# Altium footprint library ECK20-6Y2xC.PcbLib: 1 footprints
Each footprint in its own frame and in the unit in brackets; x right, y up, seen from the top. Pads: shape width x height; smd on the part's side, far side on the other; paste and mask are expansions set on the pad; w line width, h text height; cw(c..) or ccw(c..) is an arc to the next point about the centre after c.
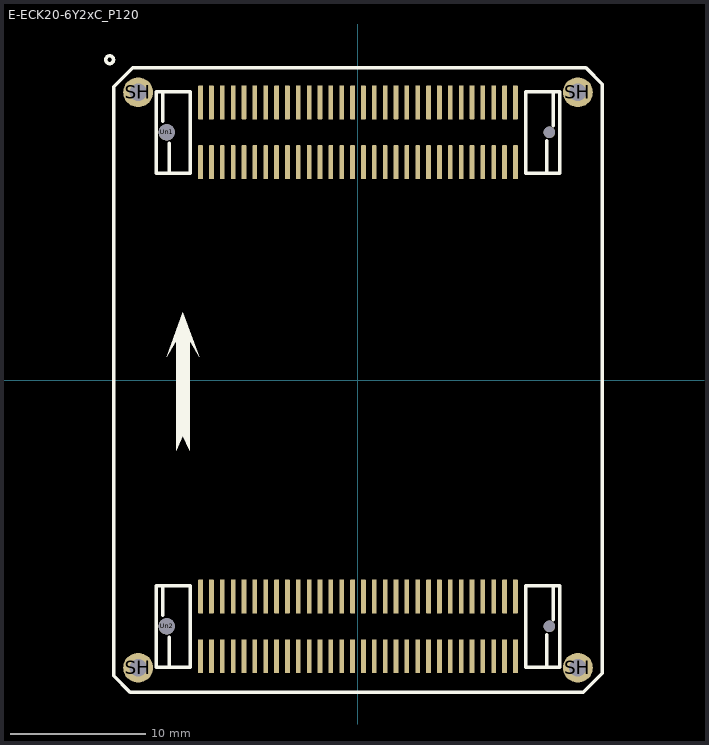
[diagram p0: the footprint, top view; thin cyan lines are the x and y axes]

## E-ECK20-6Y2xC_P120 [mm]
pads (128):
  rrect25% 0.35x2.5 smd: J1_1(-11.6,20.45) J1_2(-10.8,20.45) J1_3(-10,20.45) J1_4(-9.2,20.45) J1_5(-8.4,20.45) J1_6(-7.6,20.45) J1_7(-6.8,20.45) J1_8(-6,20.45) J1_9(-5.2,20.45) J1_10(-4.4,20.45) J1_11(-3.6,20.45) J1_12(-2.8,20.45) J1_13(-2,20.45) J1_14(-1.2,20.45) J1_15(-0.4,20.45) J1_16(0.4,20.45) J1_17(1.2,20.45) J1_18(2,20.45) J1_19(2.8,20.45) J1_20(3.6,20.45) J1_21(4.4,20.45) J1_22(5.2,20.45) J1_23(6,20.45) J1_24(6.8,20.45) J1_25(7.6,20.45) J1_26(8.4,20.45) J1_27(9.2,20.45) J1_28(10,20.45) J1_29(10.8,20.45) J1_30(11.6,20.45) J1_31(11.6,16.05) J1_32(10.8,16.05) J1_33(10,16.05) J1_34(9.2,16.05) J1_35(8.4,16.05) J1_36(7.6,16.05) J1_37(6.8,16.05) J1_38(6,16.05) J1_39(5.2,16.05) J1_40(4.4,16.05) J1_41(3.6,16.05) J1_42(2.8,16.05) J1_43(2,16.05) J1_44(1.2,16.05) J1_45(0.4,16.05) J1_46(-0.4,16.05) J1_47(-1.2,16.05) J1_48(-2,16.05) J1_49(-2.8,16.05) J1_50(-3.6,16.05) J1_51(-4.4,16.05) J1_52(-5.2,16.05) J1_53(-6,16.05) J1_54(-6.8,16.05) J1_55(-7.6,16.05) J1_56(-8.4,16.05) J1_57(-9.2,16.05) J1_58(-10,16.05) J1_59(-10.8,16.05) J1_60(-11.6,16.05) J2_1(-11.6,-15.95) J2_2(-10.8,-15.95) J2_3(-10,-15.95) J2_4(-9.2,-15.95) J2_5(-8.4,-15.95) J2_6(-7.6,-15.95) J2_7(-6.8,-15.95) J2_8(-6,-15.95) J2_9(-5.2,-15.95) J2_10(-4.4,-15.95) J2_11(-3.6,-15.95) J2_12(-2.8,-15.95) J2_13(-2,-15.95) J2_14(-1.2,-15.95) J2_15(-0.4,-15.95) J2_16(0.4,-15.95) J2_17(1.2,-15.95) J2_18(2,-15.95) J2_19(2.8,-15.95) J2_20(3.6,-15.95) J2_21(4.4,-15.95) J2_22(5.2,-15.95) J2_23(6,-15.95) J2_24(6.8,-15.95) J2_25(7.6,-15.95) J2_26(8.4,-15.95) J2_27(9.2,-15.95) J2_28(10,-15.95) J2_29(10.8,-15.95) J2_30(11.6,-15.95) J2_31(11.6,-20.35) J2_32(10.8,-20.35) J2_33(10,-20.35) J2_34(9.2,-20.35) J2_35(8.4,-20.35) J2_36(7.6,-20.35) J2_37(6.8,-20.35) J2_38(6,-20.35) J2_39(5.2,-20.35) J2_40(4.4,-20.35) J2_41(3.6,-20.35) J2_42(2.8,-20.35) J2_43(2,-20.35) J2_44(1.2,-20.35) J2_45(0.4,-20.35) J2_46(-0.4,-20.35) J2_47(-1.2,-20.35) J2_48(-2,-20.35) J2_49(-2.8,-20.35) J2_50(-3.6,-20.35) J2_51(-4.4,-20.35) J2_52(-5.2,-20.35) J2_53(-6,-20.35) J2_54(-6.8,-20.35) J2_55(-7.6,-20.35) J2_56(-8.4,-20.35) J2_57(-9.2,-20.35) J2_58(-10,-20.35) J2_59(-10.8,-20.35) J2_60(-11.6,-20.35)
  round 2.2 hole 1.3: SH(-16.2,-21.2) SH(-16.2,21.2) SH(16.2,-21.2) SH(16.2,21.2)
  round 1.2 hole 1.2: Un1(-14.1,18.25) Un2(-14.1,-18.15)
  round 0.84 hole 0.84: Un3(14.1,18.25) Un4(14.1,-18.15)
F.SilkS:
  circle w0.254: c-18.3,23.6 r0.288
  region: -11.7,1.7 -12.4,2.9 -12.4,-5.2 -12.9,-4.1 -13.4,-5.2 -13.4,2.9 -14.1,1.7 -12.9,5
  lines w0.254: -14.4,-17.35 -14.4,-15.15 ; -14.4,19.05 -14.4,21.25 ; -13.9,-21.15 -13.9,-18.95 ; -13.9,15.25 -13.9,17.45 ; -12.375,-15.175 -12.375,-21.15 -14.875,-21.15 -14.875,-15.15 -12.375,-15.15 ; -12.375,21.225 -12.375,15.25 -14.875,15.25 -14.875,21.25 -12.375,21.25 ; 13.9,-21.15 13.9,-18.75 ; 13.9,15.25 13.9,17.65 ; 14.4,-17.65 14.4,-15.15 ; 14.4,18.75 14.4,21.25 ; -18,-21.8 -16.8,-23 16.6,-23 18,-21.6 18,21.8 16.8,23 -16.6,23 -18,21.6 -18,-21.8 ; 12.375,-21.15 14.875,-21.15 14.875,-15.15 12.375,-15.15 12.375,-21.15 ; 12.375,15.25 14.875,15.25 14.875,21.25 12.375,21.25 12.375,15.25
